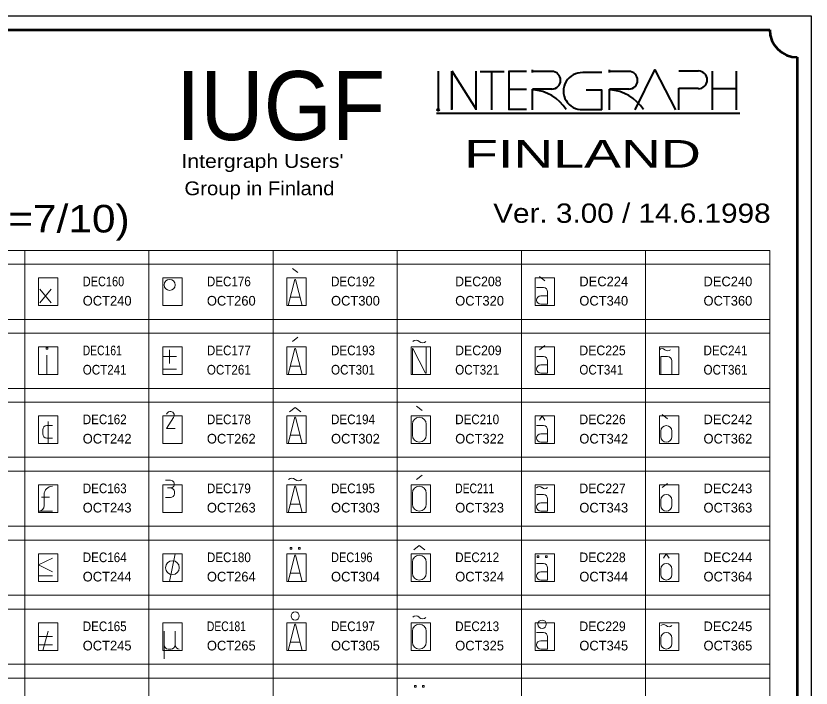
# Model space of a CAD drawing. Extents: x -200 to 7300, y -200 to 4800.
# Drawn here: x 4418 to 7300, y 2364 to 4800 of the extents above; entities that cross this region are included whole.
import ezdxf
from ezdxf.enums import TextEntityAlignment as Align

# ---------------------------------------------------------------- set-up
doc = ezdxf.new("R2010")
doc.units = 0
doc.header["$LTSCALE"] = 14
doc.header["$PDMODE"] = 32
doc.header["$PDSIZE"] = 7
for name, color, linetype, lineweight in [('1', 7, 'Continuous', 13), ('5', 7, 'Continuous', 40), ('6', 7, 'Continuous', 13), ('63', 7, 'Continuous', 13)]:
    doc.layers.add(name, color=color, linetype=linetype, lineweight=lineweight)
doc.layers.add('10', color=7, linetype='Continuous')
doc.layers.add('11', color=7, linetype='Continuous')

msp = doc.modelspace()

# ---------------------------------------------------------------- linework, layer by layer
at = {"layer": '1'}
for p, q in [((5440, 3870), (5420, 3885)), ((6335, 3840), (6315, 3855)), ((4505, 3760), (4545, 3810)), ((4505, 3810), (4545, 3760)), ((6305, 3815), (6330, 3815)), ((5413, 3780), (5448, 3780)), ((6320, 3785), (6345, 3785)), ((5420, 3620), (5440, 3635)), ((6315, 3590), (6335, 3605)), ((4975, 3540), (4975, 3590)), ((4530, 3570), (4530, 3500)), ((4950, 3565), (5000, 3565)), ((6305, 3565), (6330, 3565)), ((6795, 3550), (6795, 3500)), ((4950, 3520), (5000, 3520)), ((5413, 3530), (5448, 3530)), ((6320, 3535), (6345, 3535)), ((5890, 3370), (5870, 3385)), ((6780, 3340), (6760, 3355)), ((4550, 3315), (4530, 3315)), ((4535, 3330), (4535, 3250)), ((5855, 3320), (5855, 3280)), ((5905, 3320), (5905, 3280)), ((6305, 3315), (6330, 3315)), ((4515, 3300), (4515, 3285)), ((6755, 3295), (6755, 3275)), ((6795, 3295), (6795, 3275)), ((4530, 3270), (4550, 3270)), ((5413, 3280), (5448, 3280)), ((6320, 3285), (6345, 3285)), ((4978, 3117), (4960, 3117)), ((5870, 3120), (5890, 3135)), ((4978, 3089), (4967, 3089)), ((6760, 3090), (6780, 3105)), ((4520, 3025), (4520, 3065)), ((4992, 3075), (4992, 3068)), ((5855, 3070), (5855, 3030)), ((5905, 3070), (5905, 3030)), ((6305, 3065), (6330, 3065)), ((4510, 3055), (4540, 3055)), ((4978, 3054), (4960, 3054)), ((5413, 3030), (5448, 3030)), ((6320, 3035), (6345, 3035)), ((6755, 3045), (6755, 3025)), ((6795, 3045), (6795, 3025)), ((4550, 3005), (4500, 3005)), ((4975, 2750), (4995, 2850)), ((5855, 2820), (5855, 2780)), ((5905, 2820), (5905, 2780)), ((6305, 2815), (6330, 2815)), ((4500, 2770), (4550, 2770)), ((5413, 2780), (5448, 2780)), ((6320, 2785), (6345, 2785)), ((6755, 2795), (6755, 2775)), ((6795, 2795), (6795, 2775)), ((4515, 2500), (4535, 2570)), ((4955, 2570), (4955, 2470)), ((4995, 2570), (4995, 2520)), ((5855, 2570), (5855, 2530)), ((5905, 2570), (5905, 2530)), ((4500, 2550), (4550, 2550)), ((6305, 2565), (6330, 2565)), ((6755, 2545), (6755, 2525)), ((6795, 2545), (6795, 2525)), ((4500, 2520), (4550, 2520)), ((5413, 2530), (5448, 2530)), ((6320, 2535), (6345, 2535)), ((4970, 2505), (4980, 2505))]:
    msp.add_line(p, q, dxfattribs=at)
for points in [[(5405, 3750), (5429, 3845), (5431, 3845), (5455, 3750)], [(6345, 3800), (6345, 3755), (6320, 3755)], [(5405, 3500), (5429, 3595), (5431, 3595), (5455, 3500)], [(5855, 3500), (5855, 3595), (5857, 3595), (5902, 3505), (5905, 3505), (5905, 3600)], [(6345, 3550), (6345, 3505), (6320, 3505)], [(6755, 3500), (6755, 3565), (6780, 3565)], [(5450, 3365), (5430, 3380), (5410, 3365)], [(4995, 3304), (4964, 3304), (4989.3, 3344.9)], [(5405, 3250), (5429, 3345), (5431, 3345), (5455, 3250)], [(6335, 3335), (6325, 3350), (6315, 3335)], [(6345, 3300), (6345, 3255), (6320, 3255)], [(5405, 3000), (5429, 3095), (5431, 3095), (5455, 3000)], [(6345, 3050), (6345, 3005), (6320, 3005)], [(5900, 2865), (5880, 2880), (5860, 2865)], [(4550, 2835), (4500, 2810), (4550, 2785)], [(5405, 2750), (5429, 2845), (5431, 2845), (5455, 2750)], [(6785, 2835), (6775, 2850), (6765, 2835)], [(6345, 2800), (6345, 2755), (6320, 2755)], [(5405, 2500), (5429, 2595), (5431, 2595), (5455, 2500)], [(6345, 2550), (6345, 2505), (6320, 2505)]]:
    msp.add_lwpolyline(points, dxfattribs=at)
for points in [[(4527, 3592), (4533, 3592), (4533, 3598), (4527, 3598)], [(5412, 2867), (5418, 2867), (5418, 2873), (5412, 2873)], [(5442, 2867), (5448, 2867), (5448, 2873), (5442, 2873)], [(6307, 2837), (6313, 2837), (6313, 2843), (6307, 2843)], [(6337, 2837), (6343, 2837), (6343, 2843), (6337, 2843)], [(5862, 2367), (5868, 2367), (5868, 2373), (5862, 2373)], [(5892, 2367), (5898, 2367), (5898, 2373), (5892, 2373)]]:
    msp.add_lwpolyline(points, close=True, dxfattribs=at)
for centre, radius in [((4975, 3825), 20), ((4985, 2800), 25), ((5430, 2625), 15), ((6325, 2595), 15)]:
    msp.add_circle(centre, radius, dxfattribs=at)
for centre, radius, start, end in [((6330, 3800), 15, 0, 90), ((6320, 3770), 15, 90, 270), ((5868, 3608), 17, 45, 134.9981), ((5892, 3632), 17, 225, 314.9981), ((6760, 3580), 14.1, 45, 135), ((6780, 3600), 14.1, 225, 315), ((6330, 3550), 15, 0, 90), ((6780, 3550), 15, 0, 90), ((6320, 3520), 15, 90, 270), ((4977.5, 3352.5), 14, 327.0948, 165.9638), ((5880, 3320), 25, 0, 180), ((4530, 3300), 15, 90, 180), ((6330, 3300), 15, 0, 90), ((6775, 3295), 20, 0, 180), ((4530, 3285), 15, 180, 270), ((5880, 3280), 25, 180, 360), ((6320, 3270), 15, 90, 270), ((6775, 3275), 20, 180, 360), ((4978, 3103), 14, 265.8439, 90.0653), ((5418, 3108), 17, 45, 134.9981), ((5442, 3132), 17, 225, 314.9981), ((4550, 3065), 30, 90, 180), ((4978, 3075), 14, 0, 90), ((5880, 3070), 25, 0, 180), ((6315, 3080), 14.1, 45, 135), ((6335, 3100), 14.1, 225, 315), ((4978, 3068), 14, 270, 360), ((6330, 3050), 15, 0, 90), ((6775, 3045), 20, 0, 180), ((5880, 3030), 25, 180, 360), ((6320, 3020), 15, 90, 270), ((4500, 3025), 20, 270, 0), ((6775, 3025), 20, 180, 360), ((5880, 2820), 25, 0, 180), ((6330, 2800), 15, 0, 90), ((6775, 2795), 20, 0, 180), ((5880, 2780), 25, 180, 360), ((6320, 2770), 15, 90, 270), ((6775, 2775), 20, 180, 360), ((5868, 2608), 17, 45, 134.9981), ((5880, 2570), 25, 0, 180), ((5892, 2632), 17, 225, 314.9981), ((6765, 2580), 14.1, 45, 135), ((6785, 2600), 14.1, 225, 315), ((6330, 2550), 15, 0, 90), ((6775, 2545), 20, 0, 180), ((4970, 2520), 15, 180, 270), ((4980, 2520), 15, 270, 0), ((5010, 2520), 15, 180, 270), ((5880, 2530), 25, 180, 360), ((6320, 2520), 15, 90, 270), ((6775, 2525), 20, 180, 360)]:
    msp.add_arc(centre, radius, start, end, dxfattribs=at)
at = {"layer": '5', "lineweight": 53}
for p, q in [((-50, 4750), (7150, 4750)), ((7250, 4650), (7250, -50))]:
    msp.add_line(p, q, dxfattribs=at)
at = {"layer": '5'}
for p, q in [((5950, 4459), (5950, 4600)), ((5998, 4459), (5998, 4600)), ((5999, 4462), (5999, 4600)), ((6086, 4462), (5999, 4600)), ((6086, 4459), (6086, 4600)), ((6100, 4598), (6187, 4598)), ((6143, 4459), (6143, 4600)), ((6203, 4600), (6269, 4600)), ((6205, 4600), (6205, 4460)), ((6290, 4595), (6290, 4604)), ((6361, 4598), (6290, 4598)), ((6542, 4595), (6473, 4595)), ((6569, 4595), (6569, 4604)), ((6640, 4598), (6569, 4598)), ((6892, 4600), (6821, 4600)), ((6943, 4460), (6943, 4600)), ((7030, 4460), (7030, 4600)), ((6203, 4534), (6269, 4534)), ((6361, 4535), (6290, 4535)), ((6290, 4459), (6290, 4535)), ((6640, 4535), (6569, 4535)), ((6569, 4459), (6569, 4535)), ((6821, 4460), (6821, 4538)), ((6892, 4537), (6821, 4537)), ((6944, 4537), (7027, 4537)), ((5942, 4447), (7042, 4447)), ((6203, 4462), (6269, 4462)), ((6542, 4460), (6473, 4460))]:
    msp.add_line(p, q, dxfattribs=at)
at = {"layer": '5', "lineweight": 25}
msp.add_lwpolyline([(-200, -200), (-200, 4800), (7300, 4800), (7300, -200)], close=True, dxfattribs=at)
at = {"layer": '5'}
for points in [[(6662, 4460), (6734, 4604), (6808, 4460)], [(6662, 4460), (6734, 4604), (6808, 4460)], [(6542, 4460), (6542, 4531), (6485, 4531)]]:
    msp.add_lwpolyline(points, dxfattribs=at)
at = {"layer": '5', "lineweight": 53}
msp.add_arc((7250.2, 4750.2), 100.2, 180.1325, 269.8675, dxfattribs=at)
at = {"layer": '5'}
for centre, radius, start, end in [((6359.9, 4566.5), 32.1, 270, 90), ((6469.5, 4527.3), 67.1, 87.5556, 272.4444), ((6639.2, 4566.5), 32.1, 270, 90), ((6891.3, 4568.2), 32.1, 270, 90), ((6282.9, 4378.1), 153.8, 32.3885, 87.0195), ((6562.1, 4378.1), 153.8, 32.3885, 87.0195)]:
    msp.add_arc(centre, radius, start, end, dxfattribs=at)
msp.add_point((5948, 4460), dxfattribs=at)
at = {"layer": '6'}
for p, q in [((-50, 3950), (7150, 3950)), ((4450, 3950), (4450, -50)), ((4900, 3950), (4900, -50)), ((5350, 3950), (5350, -50)), ((5800, 3950), (5800, -50)), ((6250, 3950), (6250, -50)), ((6700, 3950), (6700, -50)), ((7150, 3950), (7150, -50)), ((-50, 3900), (7150, 3900)), ((-50, 3700), (7150, 3700)), ((-50, 3650), (7150, 3650)), ((-50, 3450), (7150, 3450)), ((-50, 3400), (7150, 3400)), ((-50, 3200), (7150, 3200)), ((-50, 3150), (7150, 3150)), ((-50, 2950), (7150, 2950)), ((-50, 2900), (7150, 2900)), ((-50, 2700), (7150, 2700)), ((-50, 2650), (7150, 2650)), ((-50, 2450), (7150, 2450)), ((-50, 2400), (7150, 2400))]:
    msp.add_line(p, q, dxfattribs=at)
at = {"layer": '63'}
for points in [[(4500, 3750), (4570, 3750), (4570, 3850), (4500, 3850)], [(4950, 3750), (5020, 3750), (5020, 3850), (4950, 3850)], [(5400, 3750), (5470, 3750), (5470, 3850), (5400, 3850)], [(6300, 3750), (6370, 3750), (6370, 3850), (6300, 3850)], [(4500, 3500), (4570, 3500), (4570, 3600), (4500, 3600)], [(4950, 3500), (5020, 3500), (5020, 3600), (4950, 3600)], [(5400, 3500), (5470, 3500), (5470, 3600), (5400, 3600)], [(5850, 3500), (5920, 3500), (5920, 3600), (5850, 3600)], [(6300, 3500), (6370, 3500), (6370, 3600), (6300, 3600)], [(6750, 3500), (6820, 3500), (6820, 3600), (6750, 3600)], [(4500, 3250), (4570, 3250), (4570, 3350), (4500, 3350)], [(4950, 3250), (5020, 3250), (5020, 3350), (4950, 3350)], [(5400, 3250), (5470, 3250), (5470, 3350), (5400, 3350)], [(5850, 3250), (5920, 3250), (5920, 3350), (5850, 3350)], [(6300, 3250), (6370, 3250), (6370, 3350), (6300, 3350)], [(6750, 3250), (6820, 3250), (6820, 3350), (6750, 3350)], [(4500, 3000), (4570, 3000), (4570, 3100), (4500, 3100)], [(4950, 3000), (5020, 3000), (5020, 3100), (4950, 3100)], [(5400, 3000), (5470, 3000), (5470, 3100), (5400, 3100)], [(5850, 3000), (5920, 3000), (5920, 3100), (5850, 3100)], [(6300, 3000), (6370, 3000), (6370, 3100), (6300, 3100)], [(6750, 3000), (6820, 3000), (6820, 3100), (6750, 3100)], [(4500, 2750), (4570, 2750), (4570, 2850), (4500, 2850)], [(4950, 2750), (5020, 2750), (5020, 2850), (4950, 2850)], [(5400, 2750), (5470, 2750), (5470, 2850), (5400, 2850)], [(5850, 2750), (5920, 2750), (5920, 2850), (5850, 2850)], [(6300, 2750), (6370, 2750), (6370, 2850), (6300, 2850)], [(6750, 2750), (6820, 2750), (6820, 2850), (6750, 2850)], [(4500, 2500), (4570, 2500), (4570, 2600), (4500, 2600)], [(4950, 2500), (5020, 2500), (5020, 2600), (4950, 2600)], [(5400, 2500), (5470, 2500), (5470, 2600), (5400, 2600)], [(5850, 2500), (5920, 2500), (5920, 2600), (5850, 2600)], [(6300, 2500), (6370, 2500), (6370, 2600), (6300, 2600)], [(6750, 2500), (6820, 2500), (6820, 2600), (6750, 2600)]]:
    msp.add_lwpolyline(points, close=True, dxfattribs=at)

# ---------------------------------------------------------------- texts
at = {"layer": '10'}
for s, width, p in [('DEC160', 0.85, (4660, 3820)), ('DEC176', 0.9, (5110, 3820)), ('DEC192', 0.9, (5560, 3820)), ('DEC208', 0.95, (6010, 3820)), ('DEC161', 0.8, (4660, 3570)), ('DEC177', 0.9, (5110, 3570)), ('DEC193', 0.9, (5560, 3570)), ('DEC209', 0.95, (6010, 3570)), ('DEC225', 0.95, (6460, 3570)), ('DEC241', 0.9, (6910, 3570)), ('DEC162', 0.9, (4660, 3320)), ('DEC178', 0.9, (5110, 3320)), ('DEC194', 0.9, (5560, 3320)), ('DEC210', 0.9, (6010, 3320)), ('DEC226', 0.95, (6460, 3320)), ('DEC163', 0.9, (4660, 3070)), ('DEC179', 0.9, (5110, 3070)), ('DEC195', 0.9, (5560, 3070)), ('DEC211', 0.8, (6010, 3070)), ('DEC227', 0.95, (6460, 3070)), ('DEC164', 0.9, (4660, 2820)), ('DEC180', 0.9, (5110, 2820)), ('DEC196', 0.85, (5560, 2820)), ('DEC212', 0.9, (6010, 2820)), ('DEC228', 0.95, (6460, 2820)), ('DEC165', 0.9, (4660, 2570)), ('DEC181', 0.8, (5110, 2570)), ('DEC197', 0.9, (5560, 2570)), ('DEC213', 0.9, (6010, 2570)), ('DEC229', 0.95, (6460, 2570))]:
    msp.add_text(s, height=35, dxfattribs=dict(at, width=width)).set_placement(p)
for s, p in [('DEC224', (6460, 3820)), ('DEC240', (6910, 3820)), ('DEC242', (6910, 3320)), ('DEC243', (6910, 3070)), ('DEC244', (6910, 2820)), ('DEC245', (6910, 2570))]:
    msp.add_text(s, height=35, dxfattribs=at).set_placement(p)
at = {"layer": '11'}
for s, p in [('OCT240', (4660, 3750)), ('OCT260', (5110, 3750)), ('OCT300', (5560, 3750)), ('OCT320', (6010, 3750)), ('OCT340', (6460, 3750)), ('OCT360', (6910, 3750)), ('OCT242', (4660, 3250)), ('OCT262', (5110, 3250)), ('OCT302', (5560, 3250)), ('OCT322', (6010, 3250)), ('OCT342', (6460, 3250)), ('OCT362', (6910, 3250)), ('OCT243', (4660, 3000)), ('OCT263', (5110, 3000)), ('OCT303', (5560, 3000)), ('OCT323', (6010, 3000)), ('OCT343', (6460, 3000)), ('OCT363', (6910, 3000)), ('OCT244', (4660, 2750)), ('OCT264', (5110, 2750)), ('OCT304', (5560, 2750)), ('OCT324', (6010, 2750)), ('OCT344', (6460, 2750)), ('OCT364', (6910, 2750)), ('OCT245', (4660, 2500)), ('OCT265', (5110, 2500)), ('OCT305', (5560, 2500)), ('OCT325', (6010, 2500)), ('OCT345', (6460, 2500)), ('OCT365', (6910, 2500))]:
    msp.add_text(s, height=35, dxfattribs=at).set_placement(p)
at = {"layer": '11', "width": 0.9}
for s, p in [('OCT241', (4660, 3500)), ('OCT261', (5110, 3500)), ('OCT301', (5560, 3500)), ('OCT321', (6010, 3500)), ('OCT341', (6460, 3500)), ('OCT361', (6910, 3500))]:
    msp.add_text(s, height=35, dxfattribs=at).set_placement(p)
at = {"layer": '5'}
for s, height, width, p in [('IUGF', 250, 0.95, (5377.5, 4350)), ('FINLAND', 100, 1.5, (6471.5, 4250)), ("Intergraph Users'", 50, 1.15, (5311.5, 4249)), ('Group in Finland', 50, 1.1, (5300.5, 4150)), ('ISO 3098 Lettering B Vertical Equal (w/h=7/10)', 100, 1.15, (3229.5, 4015))]:
    msp.add_text(s, height=height, dxfattribs=dict(at, width=width)).set_placement(p, align=Align.CENTER)
at = {"layer": '5', "width": 1.15}
msp.add_text('Ver. 3.00 / 14.6.1998', height=70, dxfattribs=at).set_placement((7153.3, 4050), align=Align.RIGHT)

doc.saveas('drawing.dxf')
